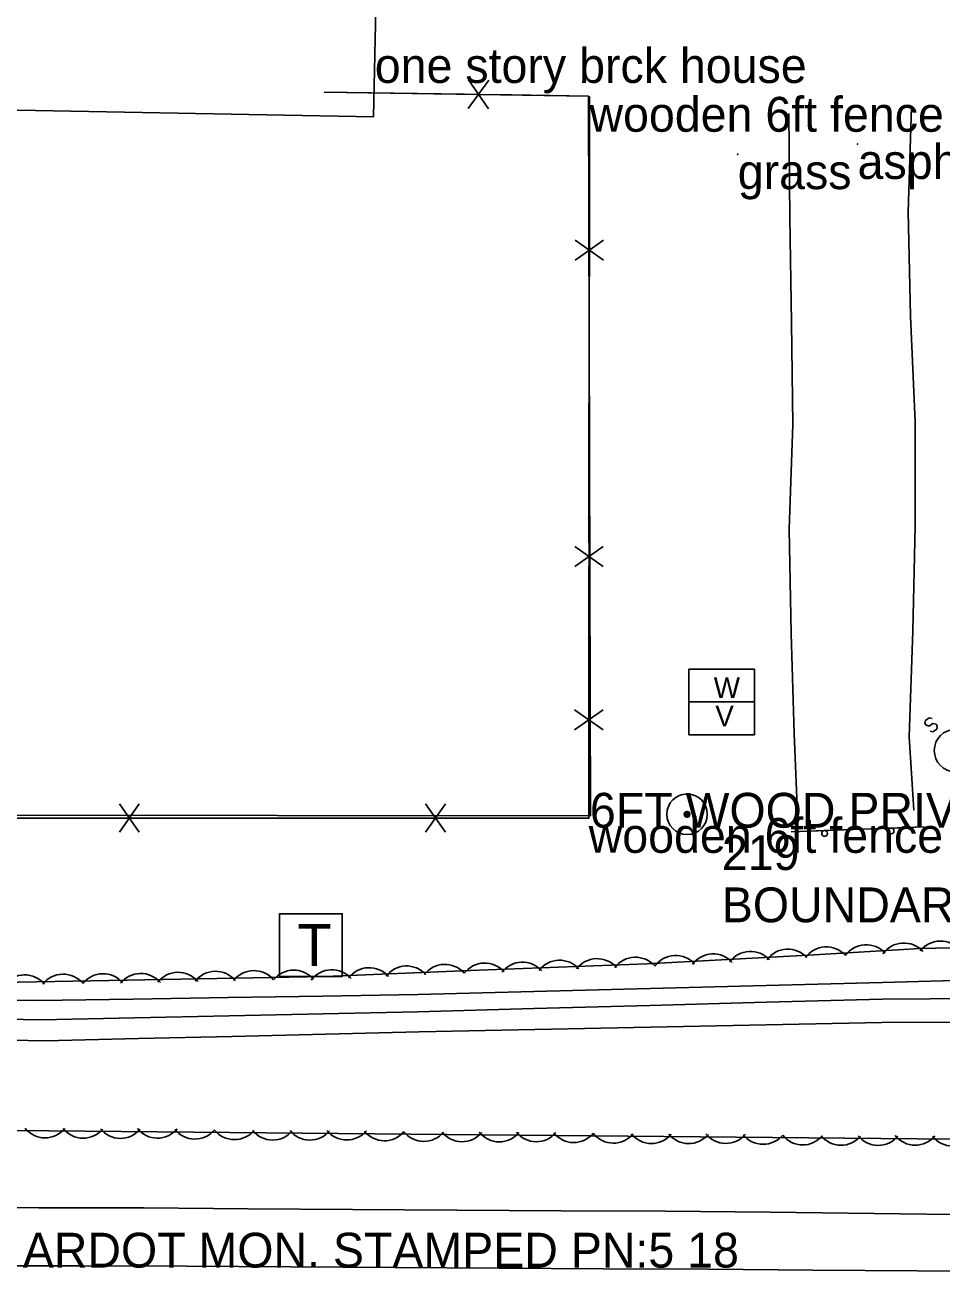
# Model space of a CAD drawing. Extents: x 1802180 to 1804859, y 572524 to 575172.
# Drawn here: x 1804301.3 to 1804433, y 573834.2 to 574014.2 of the extents above; entities that cross this region are included whole.
import ezdxf

# ---------------------------------------------------------------- set-up
doc = ezdxf.new("R2010")
doc.units = 0
for name, color, linetype in [('EX_EDGE_PAVEMENT', 7, 'Continuous'), ('EX_SHOULDER', 7, 'Continuous'), ('S_BUILDING', 7, 'Continuous'), ('S_DITCHLINE', 7, 'Continuous'), ('S_EDGE_PAVEMENT', 7, 'Continuous'), ('S_FENCE', 7, 'Continuous'), ('S_FENCE_ANNOT', 7, 'Continuous'), ('S_GUARDRAIL', 7, 'Continuous'), ('S_IRON_PIN', 7, 'Continuous'), ('S_IRON_PIN_ANNOT', 7, 'Continuous'), ('S_MSC_PT_SYM', 7, 'Continuous'), ('S_PRIMARY_CTL_ANNOT', 7, 'Continuous'), ('S_SANITARY_SEWER', 7, 'Continuous'), ('S_SURVEY_TEXT_ANNOT', 7, 'Continuous'), ('S_TELEPHONE_UTILITIES', 7, 'Continuous'), ('S_TREE', 7, 'Continuous'), ('S_WATER_UTILITIES', 7, 'Continuous')]:
    doc.layers.add(name, color=color, linetype=linetype)

msp = doc.modelspace()

# ---------------------------------------------------------------- linework, layer by layer
at = {"layer": 'EX_EDGE_PAVEMENT'}
msp.add_lwpolyline([(1804564.51, 573834.17), (1804549.51, 573834.32), (1804534.44, 573834.44), (1804519.44, 573834.55), (1804504.44, 573834.7), (1804489.43, 573834.82), (1804474.43, 573834.91), (1804459.43, 573835.03), (1804444.43, 573835.2), (1804429.46, 573835.33), (1804414.46, 573835.43), (1804399.46, 573835.55), (1804384.4, 573835.63), (1804369.4, 573835.71), (1804354.4, 573835.8), (1804339.46, 573835.89), (1804324.46, 573836.01), (1804309.46, 573836.06), (1804294.62, 573836.07)], dxfattribs=at)
at = {"layer": 'EX_SHOULDER'}
msp.add_lwpolyline([(1804265.55, 573844.85), (1804273.36, 573844.58), (1804288.27, 573844.41), (1804303.25, 573844.37), (1804318.32, 573844.38), (1804333.32, 573844.25), (1804348.29, 573844.14), (1804363.31, 573844.03), (1804378.28, 573843.94), (1804393.31, 573843.88), (1804408.33, 573843.75), (1804423.29, 573843.57), (1804438.35, 573843.38), (1804453.32, 573843.19), (1804468.29, 573843.07), (1804483.29, 573842.96), (1804498.33, 573842.85), (1804513.31, 573842.69), (1804528.29, 573842.53), (1804543.31, 573842.43), (1804558.32, 573842.29), (1804573.31, 573842.11), (1804582.3, 573842.03)], dxfattribs=at)
at = {"layer": 'S_BUILDING'}
msp.add_lwpolyline([(1804284.8, 574002.25), (1804351.35, 574001.03), (1804352.38, 574050.04), (1804327.23, 574050.19), (1804327.07, 574035.27), (1804320.62, 574035.36), (1804320.63, 574040.65), (1804285.24, 574041.03), (1804284.8, 574002.25)], dxfattribs=at)
at = {"layer": 'S_DITCHLINE'}
for points in [[(1804558.93, 573879.69), (1804544.14, 573878.96), (1804528, 573878.8), (1804511.86, 573878.65), (1804495.72, 573878.5), (1804479.58, 573878.34), (1804465.8, 573877.94), (1804452.02, 573877.53), (1804438.24, 573877.12), (1804424.46, 573876.72), (1804407.77, 573876.29), (1804391.08, 573875.85), (1804374.38, 573875.42), (1804357.69, 573874.99), (1804344.06, 573874.78), (1804330.43, 573874.56), (1804316.8, 573874.35), (1804303.17, 573874.14), (1804288.43, 573874.35)], [(1804559.05, 573876.58), (1804544.21, 573876.04), (1804527.88, 573875.7), (1804511.55, 573875.36), (1804495.21, 573875.02), (1804478.88, 573874.68), (1804465.27, 573874.59), (1804451.66, 573874.51), (1804438.05, 573874.42), (1804424.45, 573874.34), (1804407.75, 573873.89), (1804391.05, 573873.44), (1804374.35, 573872.99), (1804357.65, 573872.54), (1804344.12, 573872.25), (1804330.58, 573871.95), (1804317.05, 573871.66), (1804303.51, 573871.36), (1804288.63, 573871.65)], [(1804559.59, 573872.94), (1804544.68, 573872.27), (1804528.24, 573872.02), (1804511.79, 573871.76), (1804495.34, 573871.51), (1804478.9, 573871.25), (1804465.26, 573871.18), (1804451.63, 573871.11), (1804438, 573871.04), (1804424.36, 573870.97), (1804407.75, 573870.64), (1804391.14, 573870.31), (1804374.52, 573869.97), (1804357.91, 573869.64), (1804344.47, 573869.32), (1804331.03, 573869), (1804317.58, 573868.68), (1804304.14, 573868.36), (1804289.15, 573868.64)]]:
    msp.add_lwpolyline(points, dxfattribs=at)
at = {"layer": 'S_EDGE_PAVEMENT'}
for points in [[(1804428.64, 574002.45), (1804428.17, 573987.41), (1804428.48, 573972.4), (1804429.14, 573957.25), (1804429.18, 573942.25), (1804428.81, 573927.24), (1804428.32, 573912), (1804428.98, 573901.48)], [(1804411.03, 574001.52), (1804411.16, 573986.51), (1804411.39, 573971.5), (1804411.56, 573956.84), (1804411.05, 573941.82), (1804411.35, 573926.83), (1804411.78, 573912.5), (1804412.32, 573899.65)]]:
    msp.add_lwpolyline(points, dxfattribs=at)
at = {"layer": 'S_FENCE'}
for p, q in [((1804367.9, 574006.3), (1804364.94, 574002.21)), ((1804367.84, 574002.17), (1804365, 574006.34)), ((1804382.36, 574003.89), (1804382.25, 573900.35)), ((1804380.29, 573983.33), (1804384.38, 573980.46)), ((1804380.29, 573983.33), (1804384.38, 573980.46)), ((1804384.38, 573983.32), (1804380.29, 573980.46)), ((1804384.38, 573983.32), (1804380.29, 573980.46)), ((1804380.24, 573939.33), (1804384.34, 573936.46)), ((1804380.24, 573939.33), (1804384.34, 573936.46)), ((1804384.34, 573939.32), (1804380.24, 573936.46)), ((1804384.34, 573939.32), (1804380.24, 573936.46)), ((1804384.31, 573915.89), (1804380.21, 573913.03)), ((1804384.31, 573915.89), (1804380.21, 573913.03)), ((1804380.22, 573915.89), (1804384.31, 573913.02)), ((1804380.22, 573915.89), (1804384.31, 573913.02)), ((1804317.68, 573902.4), (1804314.82, 573898.3)), ((1804317.68, 573898.3), (1804314.82, 573902.4)), ((1804317.68, 573902.4), (1804314.82, 573898.3)), ((1804317.68, 573898.3), (1804314.82, 573902.4)), ((1804361.68, 573902.4), (1804358.82, 573898.3)), ((1804361.68, 573898.3), (1804358.82, 573902.4)), ((1804361.68, 573902.4), (1804358.82, 573898.3)), ((1804361.68, 573898.3), (1804358.82, 573902.4)), ((1804382.25, 573900.35), (1804186.39, 573900.34))]:
    msp.add_line(p, q, dxfattribs=at)
for points in [[(1804003.25, 574028.95), (1803976.65, 574029.6), (1803975.14, 573897.9), (1804070.65, 573897.42), (1804070.63, 573900.9), (1804247.6, 573900.79), (1804382.52, 573900.68), (1804382.22, 574004.01), (1804344.22, 574004.59)], [(1804364.4, 574004.29), (1804344.22, 574004.59)], [(1804382.24, 573997.61), (1804382.22, 574004.01), (1804368.44, 574004.22)], [(1804382.36, 574003.89), (1804382.34, 573983.89)], [(1804382.36, 574003.89), (1804382.34, 573983.89)], [(1804382.33, 573979.89), (1804382.29, 573939.89)], [(1804382.33, 573979.89), (1804382.29, 573939.89)], [(1804382.29, 573936.46), (1804382.27, 573916.46)], [(1804382.29, 573936.46), (1804382.27, 573916.46)], [(1804382.26, 573912.46), (1804382.25, 573900.35)], [(1804382.26, 573912.46), (1804382.25, 573900.35)], [(1804314.82, 573900.35), (1804294.82, 573900.35)], [(1804314.82, 573900.35), (1804294.82, 573900.35)], [(1804358.25, 573900.35), (1804318.25, 573900.35)], [(1804358.25, 573900.35), (1804318.25, 573900.35)], [(1804382.25, 573900.35), (1804362.25, 573900.35)], [(1804382.25, 573900.35), (1804362.25, 573900.35)]]:
    msp.add_lwpolyline(points, dxfattribs=at)
at = {"layer": 'S_GUARDRAIL'}
msp.add_line((1804430.45, 573899.09), (1804411.36, 573898.38), dxfattribs=at)
for points in [[(1804416.13, 573898.56), (1804411.36, 573898.38)], [(1804425.68, 573898.91), (1804416.13, 573898.56)], [(1804430.45, 573899.09), (1804425.68, 573898.91)]]:
    msp.add_lwpolyline(points, dxfattribs=at)
for centre in [(1804416.15, 573898.14), (1804425.7, 573898.49)]:
    msp.add_circle(centre, 0.42, dxfattribs=at)
at = {"layer": 'S_IRON_PIN'}
for radius in [2.91, 0.411, 0.262, 0.212, 0.145, 0.0822, 0.0581]:
    msp.add_circle((1804396.38, 573900.88), radius, dxfattribs=at)
at = {"layer": 'S_MSC_PT_SYM'}
for points in [[(1804351.51, 574010.9), (1804351.51, 574010.95), (1804351.51, 574010.9), (1804351.46, 574010.9), (1804351.51, 574010.9), (1804351.51, 574010.85), (1804351.51, 574010.9), (1804351.56, 574010.9)], [(1804382.36, 574003.89), (1804382.36, 574003.94), (1804382.36, 574003.89), (1804382.31, 574003.89), (1804382.36, 574003.89), (1804382.36, 574003.84), (1804382.36, 574003.89), (1804382.41, 574003.89)], [(1804420.89, 573997.11), (1804420.89, 573997.16), (1804420.89, 573997.11), (1804420.84, 573997.11), (1804420.89, 573997.11), (1804420.89, 573997.06), (1804420.89, 573997.11), (1804420.94, 573997.11)], [(1804403.67, 573995.65), (1804403.67, 573995.7), (1804403.67, 573995.65), (1804403.62, 573995.65), (1804403.67, 573995.65), (1804403.67, 573995.6), (1804403.67, 573995.65), (1804403.72, 573995.65)], [(1804382.42, 573903.96), (1804382.42, 573904.01), (1804382.42, 573903.96), (1804382.37, 573903.96), (1804382.42, 573903.96), (1804382.42, 573903.91), (1804382.42, 573903.96), (1804382.47, 573903.96)], [(1804382.25, 573900.35), (1804382.25, 573900.4), (1804382.25, 573900.35), (1804382.2, 573900.35), (1804382.25, 573900.35), (1804382.25, 573900.3), (1804382.25, 573900.35), (1804382.3, 573900.35)]]:
    msp.add_lwpolyline(points, dxfattribs=at)
at = {"layer": 'S_SANITARY_SEWER'}
for p, q in [((1804430.63, 573914.33), (1804430.55, 573913.95)), ((1804430.55, 573913.95), (1804430.75, 573913.67)), ((1804431.17, 573914.72), (1804430.63, 573914.33)), ((1804431.6, 573914.64), (1804431.17, 573914.72)), ((1804431.17, 573913.56), (1804431.71, 573913.91)), ((1804431.71, 573913.91), (1804432.18, 573913.83)), ((1804432.18, 573913.83), (1804432.33, 573913.56)), ((1804430.75, 573913.67), (1804431.17, 573913.56)), ((1804431.71, 573912.74), (1804431.33, 573912.82)), ((1804432.26, 573913.13), (1804431.71, 573912.74)), ((1804432.33, 573913.56), (1804432.26, 573913.13))]:
    msp.add_line(p, q, dxfattribs=at)
msp.add_circle((1804434.96, 573910.03), 3.05, dxfattribs=at)
at = {"layer": 'S_TELEPHONE_UTILITIES'}
msp.add_lwpolyline([(1804337.83, 573877.61), (1804337.83, 573886.61), (1804346.83, 573886.61), (1804346.83, 573877.61)], close=True, dxfattribs=at)
at = {"layer": 'S_TREE'}
for points in [[(1804028.96, 573857.37), (1803940.77, 573858.42), (1803923.97, 573858.58), (1803910.57, 573858.02), (1803901.91, 573857.92), (1803900.12, 573861.4), (1803900.53, 573864.85), (1803905.76, 573869.1), (1803923.73, 573869.56), (1803952.28, 573870.21), (1803968.67, 573874.97), (1803977.07, 573881.31), (1803984.3, 573883.33), (1804072.24, 573880.43), (1804160.36, 573877.32), (1804264.02, 573876.11), (1804344.36, 573877.6), (1804365.24, 573878.46), (1804390.61, 573879.39), (1804413.82, 573880.66), (1804429.89, 573881.62), (1804461.37, 573882.29), (1804473.87, 573881.54)], [(1804491.81, 573853.7), (1804252.68, 573855.92), (1804176.89, 573855.49), (1804029.05, 573857.29)]]:
    msp.add_lwpolyline(points, dxfattribs=at)
for centre, radius, start, end in [((1804410.87, 573877.83), 3.7, 42.3185, 143.9154), ((1804416.4, 573878.14), 3.7, 42.6261, 144.223), ((1804422.12, 573878.45), 3.7, 42.6261, 144.223), ((1804427.53, 573878.7), 3.7, 42.6261, 144.223), ((1804432.78, 573878.98), 3.7, 40.419, 142.0159), ((1804372.72, 573875.96), 3.7, 41.3073, 142.9042), ((1804378.07, 573876.23), 3.7, 41.3073, 142.9042), ((1804383.45, 573876.46), 3.7, 41.3073, 142.9042), ((1804388.97, 573876.66), 3.7, 41.3073, 142.9042), ((1804394.74, 573876.91), 3.7, 42.3185, 143.9154), ((1804400.15, 573877.13), 3.7, 42.3185, 143.9154), ((1804405.5, 573877.5), 3.7, 42.3185, 143.9154), ((1804301.21, 573874.13), 3.7, 40.2634, 141.8603), ((1804306.73, 573874.23), 3.7, 40.2634, 141.8603), ((1804312.46, 573874.3), 3.7, 40.2634, 141.8603), ((1804317.88, 573874.33), 3.7, 40.2634, 141.8603), ((1804323.24, 573874.5), 3.7, 40.2634, 141.8603), ((1804328.62, 573874.64), 3.7, 40.2634, 141.8603), ((1804334.14, 573874.74), 3.7, 40.2634, 141.8603), ((1804339.87, 573874.81), 3.7, 40.2634, 141.8603), ((1804345.34, 573874.86), 3.7, 41.5643, 143.1612), ((1804350.7, 573875.16), 3.7, 41.5643, 143.1612), ((1804356.07, 573875.41), 3.7, 41.5643, 143.1612), ((1804361.59, 573875.64), 3.7, 41.5643, 143.1612), ((1804367.31, 573875.83), 3.7, 41.3073, 142.9042), ((1804304.13, 573858.09), 3.67, 218.6696, 320.2665), ((1804309.61, 573858.04), 3.67, 218.6696, 320.2665), ((1804314.96, 573858.02), 3.67, 218.6696, 320.2665), ((1804320.28, 573858.05), 3.67, 218.6696, 320.2665), ((1804325.66, 573857.92), 3.67, 218.6696, 320.2665), ((1804331.35, 573857.84), 3.67, 218.6696, 320.2665), ((1804336.83, 573857.78), 3.67, 218.6696, 320.2665), ((1804342.18, 573857.77), 3.67, 218.6696, 320.2665), ((1804347.5, 573857.79), 3.67, 218.6696, 320.2665), ((1804352.88, 573857.67), 3.67, 218.6696, 320.2665), ((1804358.57, 573857.59), 3.67, 218.6696, 320.2665), ((1804364.05, 573857.53), 3.67, 218.6696, 320.2665), ((1804369.4, 573857.52), 3.67, 218.6696, 320.2665), ((1804374.72, 573857.54), 3.67, 218.6696, 320.2665), ((1804380.1, 573857.42), 3.67, 218.6696, 320.2665), ((1804385.79, 573857.33), 3.67, 218.6696, 320.2665), ((1804391.27, 573857.28), 3.67, 218.6696, 320.2665), ((1804396.62, 573857.27), 3.67, 218.6696, 320.2665), ((1804401.95, 573857.29), 3.67, 218.6696, 320.2665), ((1804407.32, 573857.17), 3.67, 218.6696, 320.2665), ((1804413.01, 573857.08), 3.67, 218.6696, 320.2665), ((1804418.5, 573857.03), 3.67, 218.6696, 320.2665), ((1804423.84, 573857.01), 3.67, 218.6696, 320.2665), ((1804429.17, 573857.04), 3.67, 218.6696, 320.2665), ((1804434.54, 573856.91), 3.67, 218.6696, 320.2665)]:
    msp.add_arc(centre, radius, start, end, dxfattribs=at)
at = {"layer": 'S_WATER_UTILITIES'}
for p, q in [((1804396.66, 573921.72), (1804406.07, 573921.72)), ((1804396.66, 573912.3), (1804396.66, 573921.72)), ((1804406.07, 573921.72), (1804406.07, 573912.3)), ((1804396.66, 573917.03), (1804406.07, 573917.03)), ((1804406.07, 573912.3), (1804396.66, 573912.3))]:
    msp.add_line(p, q, dxfattribs=at)

# ---------------------------------------------------------------- texts
at = {"layer": 'S_FENCE_ANNOT'}
for s, p in [('wooden 6ft fence', (1804382.36, 573998.89)), ('wooden 6ft fence ', (1804382.25, 573895.35))]:
    msp.add_text(s, height=5, dxfattribs=at).set_placement(p)
at = {"layer": 'S_IRON_PIN_ANNOT'}
for s, p in [('219', (1804401.38, 573892.88)), ('BOUNDARY MONUMENT/REBAR ALUMINU ', (1804401.38, 573885.38))]:
    msp.add_text(s, height=5, dxfattribs=at).set_placement(p)
at = {"layer": 'S_PRIMARY_CTL_ANNOT'}
msp.add_text('PD:STD ARDOT MON. STAMPED PN:5 18', height=5, dxfattribs=at).set_placement((1804274.55, 573835.8))
at = {"layer": 'S_SURVEY_TEXT_ANNOT'}
for s, p in [('one story brck house', (1804351.51, 574005.9)), ('asphalt roadway', (1804420.89, 573992.11)), ('grass', (1804403.67, 573990.65)), ('6FT WOOD PRIVACY FENCE ', (1804382.42, 573898.96))]:
    msp.add_text(s, height=5, dxfattribs=at).set_placement(p)
at = {"layer": 'S_TELEPHONE_UTILITIES'}
msp.add_text('T', height=6, rotation=360, dxfattribs=at).set_placement((1804340.39, 573879.11))
at = {"layer": 'S_WATER_UTILITIES'}
for s, p in [('W', (1804400.21, 573917.56)), ('V', (1804400.44, 573913.5))]:
    msp.add_text(s, height=3, rotation=360, dxfattribs=at).set_placement(p)

doc.saveas('drawing.dxf')
